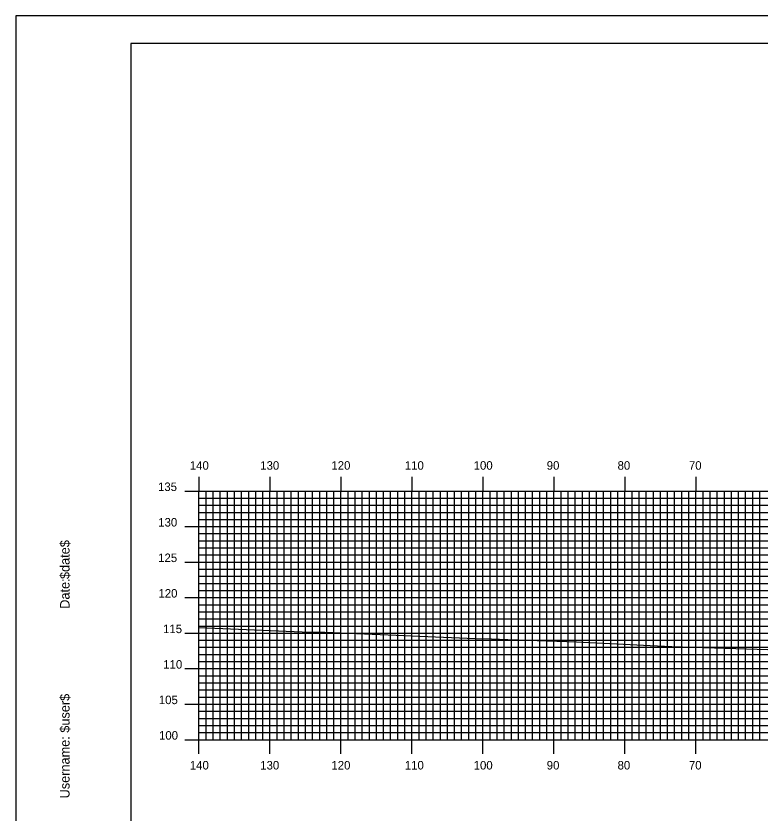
# Model space of a CAD drawing. Extents: x 1781073 to 1781416, y 442591 to 442811.
# Drawn here: x 1781073.1 to 1781177.9, y 442698.3 to 442810.5 of the extents above; entities that cross this region are included whole.
import ezdxf

# ---------------------------------------------------------------- set-up
doc = ezdxf.new("R2010")
doc.units = 0
for name, color, linetype in [('BORDER', 7, 'Continuous'), ('H_V ANNOTATION', 7, 'Continuous'), ('MAJOR', 7, 'Continuous'), ('MINOR', 7, 'Continuous'), ('PLOT BOUNDARY', 7, 'Continuous'), ('S_Roadway_Centerline', 7, 'Continuous')]:
    doc.layers.add(name, color=color, linetype=linetype)

msp = doc.modelspace()

# ---------------------------------------------------------------- linework, layer by layer
at = {"layer": 'BORDER'}
msp.add_lwpolyline([(1781089.29, 442596.67), (1781409.29, 442596.67), (1781409.29, 442806.67), (1781089.29, 442806.67)], close=True, dxfattribs=at)
at = {"layer": 'MAJOR'}
for p, q in [((1781098.89, 442745.67), (1781098.89, 442743.67)), ((1781108.89, 442745.67), (1781108.89, 442743.67)), ((1781118.89, 442745.67), (1781118.89, 442743.67)), ((1781128.89, 442745.67), (1781128.89, 442743.67)), ((1781138.89, 442745.67), (1781138.89, 442743.67)), ((1781148.89, 442745.67), (1781148.89, 442743.67)), ((1781158.89, 442745.67), (1781158.89, 442743.67)), ((1781168.89, 442745.67), (1781168.89, 442743.67)), ((1781096.89, 442743.67), (1781098.89, 442743.67)), ((1781098.89, 442743.67), (1781378.89, 442743.67)), ((1781098.89, 442708.67), (1781098.89, 442743.67)), ((1781098.89, 442708.67), (1781098.89, 442743.67)), ((1781098.89, 442743.67), (1781378.89, 442743.67)), ((1781108.89, 442708.67), (1781108.89, 442743.67)), ((1781118.89, 442708.67), (1781118.89, 442743.67)), ((1781128.89, 442708.67), (1781128.89, 442743.67)), ((1781138.89, 442708.67), (1781138.89, 442743.67)), ((1781148.89, 442708.67), (1781148.89, 442743.67)), ((1781158.89, 442708.67), (1781158.89, 442743.67)), ((1781168.89, 442708.67), (1781168.89, 442743.67)), ((1781096.89, 442738.67), (1781098.89, 442738.67)), ((1781098.89, 442738.67), (1781378.89, 442738.67)), ((1781096.89, 442733.67), (1781098.89, 442733.67)), ((1781098.89, 442733.67), (1781378.89, 442733.67)), ((1781096.89, 442728.67), (1781098.89, 442728.67)), ((1781098.89, 442728.67), (1781378.89, 442728.67)), ((1781096.89, 442723.67), (1781098.89, 442723.67)), ((1781098.89, 442723.67), (1781378.89, 442723.67)), ((1781096.89, 442718.67), (1781098.89, 442718.67)), ((1781098.89, 442718.67), (1781378.89, 442718.67)), ((1781096.89, 442713.67), (1781098.89, 442713.67)), ((1781098.89, 442713.67), (1781378.89, 442713.67)), ((1781096.89, 442708.67), (1781098.89, 442708.67)), ((1781098.89, 442708.67), (1781378.89, 442708.67)), ((1781098.89, 442708.67), (1781378.89, 442708.67)), ((1781098.89, 442706.66), (1781098.89, 442708.67)), ((1781108.89, 442706.66), (1781108.89, 442708.67)), ((1781118.89, 442706.66), (1781118.89, 442708.67)), ((1781128.89, 442706.66), (1781128.89, 442708.67)), ((1781138.89, 442706.66), (1781138.89, 442708.67)), ((1781148.89, 442706.66), (1781148.89, 442708.67)), ((1781158.89, 442706.66), (1781158.89, 442708.67)), ((1781168.89, 442706.66), (1781168.89, 442708.67))]:
    msp.add_line(p, q, dxfattribs=at)
at = {"layer": 'MINOR'}
for p, q in [((1781099.89, 442708.67), (1781099.89, 442743.67)), ((1781100.89, 442708.67), (1781100.89, 442743.67)), ((1781101.89, 442708.67), (1781101.89, 442743.67)), ((1781102.89, 442708.67), (1781102.89, 442743.67)), ((1781103.89, 442708.67), (1781103.89, 442743.67)), ((1781104.89, 442708.67), (1781104.89, 442743.67)), ((1781105.89, 442708.67), (1781105.89, 442743.67)), ((1781106.89, 442708.67), (1781106.89, 442743.67)), ((1781107.89, 442708.67), (1781107.89, 442743.67)), ((1781109.89, 442708.67), (1781109.89, 442743.67)), ((1781110.89, 442708.67), (1781110.89, 442743.67)), ((1781111.89, 442708.67), (1781111.89, 442743.67)), ((1781112.89, 442708.67), (1781112.89, 442743.67)), ((1781113.89, 442708.67), (1781113.89, 442743.67)), ((1781114.89, 442708.67), (1781114.89, 442743.67)), ((1781115.89, 442708.67), (1781115.89, 442743.67)), ((1781116.89, 442708.67), (1781116.89, 442743.67)), ((1781117.89, 442708.67), (1781117.89, 442743.67)), ((1781119.89, 442708.67), (1781119.89, 442743.67)), ((1781120.89, 442708.67), (1781120.89, 442743.67)), ((1781121.89, 442708.67), (1781121.89, 442743.67)), ((1781122.89, 442708.67), (1781122.89, 442743.67)), ((1781123.89, 442708.67), (1781123.89, 442743.67)), ((1781124.89, 442708.67), (1781124.89, 442743.67)), ((1781125.89, 442708.67), (1781125.89, 442743.67)), ((1781126.89, 442708.67), (1781126.89, 442743.67)), ((1781127.89, 442708.67), (1781127.89, 442743.67)), ((1781129.89, 442708.67), (1781129.89, 442743.67)), ((1781130.89, 442708.67), (1781130.89, 442743.67)), ((1781131.89, 442708.67), (1781131.89, 442743.67)), ((1781132.89, 442708.67), (1781132.89, 442743.67)), ((1781133.89, 442708.67), (1781133.89, 442743.67)), ((1781134.89, 442708.67), (1781134.89, 442743.67)), ((1781135.89, 442708.67), (1781135.89, 442743.67)), ((1781136.89, 442708.67), (1781136.89, 442743.67)), ((1781137.89, 442708.67), (1781137.89, 442743.67)), ((1781139.89, 442708.67), (1781139.89, 442743.67)), ((1781140.89, 442708.67), (1781140.89, 442743.67)), ((1781141.89, 442708.67), (1781141.89, 442743.67)), ((1781142.89, 442708.67), (1781142.89, 442743.67)), ((1781143.89, 442708.67), (1781143.89, 442743.67)), ((1781144.89, 442708.67), (1781144.89, 442743.67)), ((1781145.89, 442708.67), (1781145.89, 442743.67)), ((1781146.89, 442708.67), (1781146.89, 442743.67)), ((1781147.89, 442708.67), (1781147.89, 442743.67)), ((1781149.89, 442708.67), (1781149.89, 442743.67)), ((1781150.89, 442708.67), (1781150.89, 442743.67)), ((1781151.89, 442708.67), (1781151.89, 442743.67)), ((1781152.89, 442708.67), (1781152.89, 442743.67)), ((1781153.89, 442708.67), (1781153.89, 442743.67)), ((1781154.89, 442708.67), (1781154.89, 442743.67)), ((1781155.89, 442708.67), (1781155.89, 442743.67)), ((1781156.89, 442708.67), (1781156.89, 442743.67)), ((1781157.89, 442708.67), (1781157.89, 442743.67)), ((1781159.89, 442708.67), (1781159.89, 442743.67)), ((1781160.89, 442708.67), (1781160.89, 442743.67)), ((1781161.89, 442708.67), (1781161.89, 442743.67)), ((1781162.89, 442708.67), (1781162.89, 442743.67)), ((1781163.89, 442708.67), (1781163.89, 442743.67)), ((1781164.89, 442708.67), (1781164.89, 442743.67)), ((1781165.89, 442708.67), (1781165.89, 442743.67)), ((1781166.89, 442708.67), (1781166.89, 442743.67)), ((1781167.89, 442708.67), (1781167.89, 442743.67)), ((1781169.89, 442708.67), (1781169.89, 442743.67)), ((1781170.89, 442708.67), (1781170.89, 442743.67)), ((1781171.89, 442708.67), (1781171.89, 442743.67)), ((1781172.89, 442708.67), (1781172.89, 442743.67)), ((1781173.89, 442708.67), (1781173.89, 442743.67)), ((1781174.89, 442708.67), (1781174.89, 442743.67)), ((1781175.89, 442708.67), (1781175.89, 442743.67)), ((1781176.89, 442708.67), (1781176.89, 442743.67)), ((1781177.89, 442708.67), (1781177.89, 442743.67)), ((1781098.89, 442742.67), (1781378.89, 442742.67)), ((1781098.89, 442742.67), (1781100.9, 442742.67)), ((1781098.89, 442741.67), (1781378.89, 442741.67)), ((1781098.89, 442741.67), (1781100.9, 442741.67)), ((1781098.89, 442740.67), (1781378.89, 442740.67)), ((1781098.89, 442740.67), (1781100.9, 442740.67)), ((1781098.89, 442739.67), (1781378.89, 442739.67)), ((1781098.89, 442739.67), (1781100.9, 442739.67)), ((1781098.89, 442737.67), (1781378.89, 442737.67)), ((1781098.89, 442737.67), (1781100.9, 442737.67)), ((1781098.89, 442736.67), (1781378.89, 442736.67)), ((1781098.89, 442736.67), (1781100.9, 442736.67)), ((1781098.89, 442735.67), (1781378.89, 442735.67)), ((1781098.89, 442735.67), (1781100.9, 442735.67)), ((1781098.89, 442734.67), (1781378.89, 442734.67)), ((1781098.89, 442734.67), (1781100.9, 442734.67)), ((1781098.89, 442732.67), (1781378.89, 442732.67)), ((1781098.89, 442732.67), (1781100.9, 442732.67)), ((1781098.89, 442731.67), (1781378.89, 442731.67)), ((1781098.89, 442731.67), (1781100.9, 442731.67)), ((1781098.89, 442730.67), (1781378.89, 442730.67)), ((1781098.89, 442730.67), (1781100.9, 442730.67)), ((1781098.89, 442729.67), (1781378.89, 442729.67)), ((1781098.89, 442729.67), (1781100.9, 442729.67)), ((1781098.89, 442727.67), (1781378.89, 442727.67)), ((1781098.89, 442727.67), (1781100.9, 442727.67)), ((1781098.89, 442726.67), (1781378.89, 442726.67)), ((1781098.89, 442726.67), (1781100.9, 442726.67)), ((1781098.89, 442725.67), (1781378.89, 442725.67)), ((1781098.89, 442725.67), (1781100.9, 442725.67)), ((1781098.89, 442724.67), (1781378.89, 442724.67)), ((1781098.89, 442724.67), (1781100.9, 442724.67)), ((1781098.89, 442722.67), (1781378.89, 442722.67)), ((1781098.89, 442722.67), (1781100.9, 442722.67)), ((1781098.89, 442721.67), (1781378.89, 442721.67)), ((1781098.89, 442721.67), (1781100.9, 442721.67)), ((1781098.89, 442720.67), (1781378.89, 442720.67)), ((1781098.89, 442720.67), (1781100.9, 442720.67)), ((1781098.89, 442719.67), (1781378.89, 442719.67)), ((1781098.89, 442719.67), (1781100.9, 442719.67)), ((1781098.89, 442717.67), (1781378.89, 442717.67)), ((1781098.89, 442717.67), (1781100.9, 442717.67)), ((1781098.89, 442716.67), (1781378.89, 442716.67)), ((1781098.89, 442716.67), (1781100.9, 442716.67)), ((1781098.89, 442715.67), (1781378.89, 442715.67)), ((1781098.89, 442715.67), (1781100.9, 442715.67)), ((1781098.89, 442714.67), (1781378.89, 442714.67)), ((1781098.89, 442714.67), (1781100.9, 442714.67)), ((1781098.89, 442712.67), (1781378.89, 442712.67)), ((1781098.89, 442712.67), (1781100.9, 442712.67)), ((1781098.89, 442711.67), (1781378.89, 442711.67)), ((1781098.89, 442711.67), (1781100.9, 442711.67)), ((1781098.89, 442710.67), (1781378.89, 442710.67)), ((1781098.89, 442710.67), (1781100.9, 442710.67)), ((1781098.89, 442709.67), (1781378.89, 442709.67)), ((1781098.89, 442709.67), (1781100.9, 442709.67))]:
    msp.add_line(p, q, dxfattribs=at)
at = {"layer": 'PLOT BOUNDARY'}
msp.add_lwpolyline([(1781073.11, 442590.55), (1781413.11, 442590.55), (1781413.11, 442810.55), (1781073.11, 442810.55)], close=True, dxfattribs=at)
at = {"layer": 'S_Roadway_Centerline'}
msp.add_lwpolyline([(1781098.89, 442724.47), (1781114.53, 442723.8), (1781116.6, 442723.78), (1781137.78, 442722.9), (1781140.1, 442722.85), (1781142.38, 442722.75), (1781152.05, 442722.43), (1781162.45, 442721.93), (1781165.48, 442721.8), (1781185.02, 442721.19)], dxfattribs=at)

# ---------------------------------------------------------------- texts
at = {"layer": 'BORDER'}
for s, p in [('$date$', (1781080.66, 442731.28)), ('Date:', (1781080.66, 442727.1)), ('$user$', (1781080.66, 442709.65)), ('Username:', (1781080.66, 442700.4))]:
    msp.add_text(s, height=1.339, rotation=90, dxfattribs=at).set_placement(p)
at = {"layer": 'H_V ANNOTATION'}
for s, p in [('140', (1781097.6, 442746.67)), ('130', (1781107.52, 442746.67)), ('120', (1781117.54, 442746.67)), ('110', (1781127.88, 442746.67)), ('100', (1781137.58, 442746.67)), ('90', (1781147.87, 442746.67)), ('80', (1781157.85, 442746.67)), ('70', (1781167.9, 442746.67)), ('135', (1781093.12, 442743.67)), ('130', (1781093.15, 442738.67)), ('125', (1781093.14, 442733.67)), ('120', (1781093.18, 442728.67)), ('115', (1781093.83, 442723.67)), ('110', (1781093.86, 442718.67)), ('105', (1781093.23, 442713.67)), ('100', (1781093.26, 442708.67)), ('140', (1781097.6, 442704.47)), ('130', (1781107.52, 442704.47)), ('120', (1781117.54, 442704.47)), ('110', (1781127.88, 442704.47)), ('100', (1781137.58, 442704.47)), ('90', (1781147.87, 442704.47)), ('80', (1781157.85, 442704.47)), ('70', (1781167.9, 442704.47))]:
    msp.add_text(s, height=1.2, dxfattribs=at).set_placement(p)
at = {"layer": 'MAJOR'}
msp.add_text('-', height=0.012, dxfattribs=at).set_placement((1781098.89, 442708.67))

doc.saveas('drawing.dxf')
